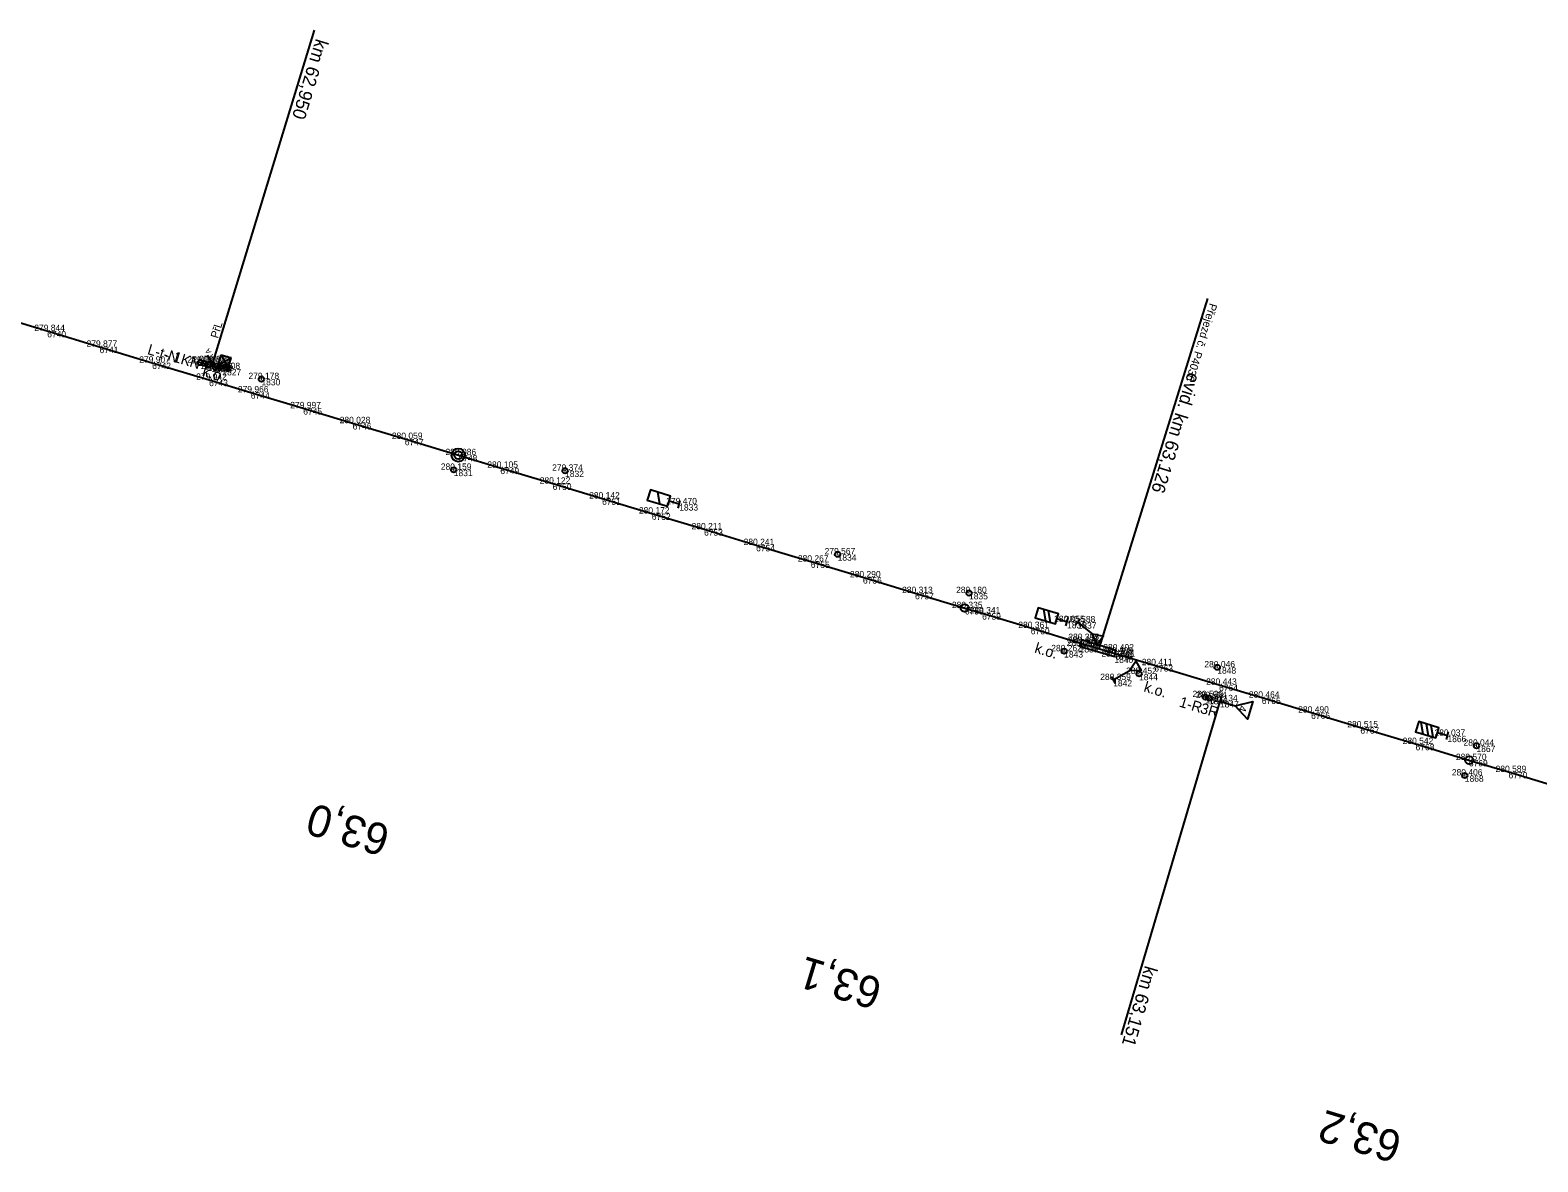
# Model space of a CAD drawing. Extents: x -613968 to -612840, y -1056667 to -1056202.
# Drawn here: x -613407.7 to -613122.4, y -1056605.8 to -1056391.6 of the extents above; entities that cross this region are included whole.
import ezdxf

# ---------------------------------------------------------------- set-up
doc = ezdxf.new("R2010")
doc.units = 0
for name, color, linetype in [('Deska žb', 7, 'Continuous'), ('Rozpiska_pole_2', 7, 'Continuous'), ('Rozpiska_pole_5', 7, 'Continuous'), ('Rozpiska_pole_7', 7, 'Continuous'), ('Vrstva 1', 7, 'Continuous'), ('Vrstva 27', 7, 'Continuous'), ('Vrstva 49', 7, 'Continuous'), ('Vrstva 50', 7, 'Continuous'), ('Vrstva 60', 7, 'Continuous'), ('Vrstva 61', 7, 'Continuous')]:
    doc.layers.add(name, color=color, linetype=linetype)

msp = doc.modelspace()

# ---------------------------------------------------------------- linework, layer by layer
for p, q in [((-613205.42, -1056508.66), (-613184.86, -1056442.36)), ((-613208.99, -1056503.07), (-613209.96, -1056504.28)), ((-613203.12, -1056513.92), (-613202.36, -1056515.28))]:
    msp.add_line(p, q)
for points in [[(-613209.47, -1056503.68), (-613206.75, -1056505.84), (-613204.56, -1056506.31), (-613205.8, -1056507.88), (-613206.75, -1056505.84)], [(-613202.74, -1056514.6), (-613199.72, -1056512.89), (-613198.45, -1056511.05), (-613197.47, -1056512.78), (-613199.72, -1056512.89)]]:
    msp.add_lwpolyline(points)
msp.add_lwpolyline([(-613208.77, -1056507.03), (-613209.1, -1056508.19), (-613202.51, -1056510.17), (-613202.17, -1056509.01)], close=True)
at = {"layer": 'Deska žb'}
for p, q in [((-613182.54, -1056518.62), (-613201.21, -1056581.77)), ((-613182.33, -1056517.9), (-613182.76, -1056519.33))]:
    msp.add_line(p, q, dxfattribs=at)
msp.add_lwpolyline([(-613182.54, -1056518.62), (-613179.67, -1056519.48), (-613176.29, -1056518.67), (-613177.31, -1056522.02), (-613179.67, -1056519.48)], dxfattribs=at)
at = {"layer": 'Rozpiska_pole_2'}
msp.add_lwpolyline([(-613373.29, -1056454.43), (-613373.43, -1056455.09), (-613373.04, -1056455.18), (-613372.84, -1056454.6)], close=True, dxfattribs=at)
at = {"layer": 'Rozpiska_pole_5'}
for p, q in [((-613373.19, -1056454.81), (-613353.93, -1056391.59)), ((-613374.19, -1056453.11), (-613373.19, -1056454.81)), ((-613373.62, -1056455.07), (-613372.76, -1056454.56))]:
    msp.add_line(p, q, dxfattribs=at)
at = {"layer": 'Rozpiska_pole_7'}
for p, q in [((-613372.15, -1056454.97), (-613371.57, -1056453.05)), ((-613372.15, -1056454.97), (-613369.66, -1056453.63)), ((-613371.57, -1056453.05), (-613369.66, -1056453.63)), ((-613371.57, -1056453.05), (-613370.24, -1056455.55)), ((-613370.24, -1056455.55), (-613369.66, -1056453.63)), ((-613372.06, -1056455.52), (-613372.53, -1056455.38)), ((-613372.15, -1056454.97), (-613372.3, -1056455.45)), ((-613372.15, -1056454.97), (-613370.24, -1056455.55)), ((-613370.14, -1056456.1), (-613370.62, -1056455.95)), ((-613370.24, -1056455.55), (-613370.38, -1056456.03)), ((-613327.6, -1056474.81), (-613327.5, -1056474.83)), ((-613288.52, -1056481.28), (-613288.9, -1056479.07)), ((-613285.1, -1056482.05), (-613284.67, -1056480.61)), ((-613230.07, -1056498.14), (-613229.98, -1056498.17)), ((-613215.96, -1056501.22), (-613215.58, -1056503.43)), ((-613214.62, -1056503.72), (-613215, -1056501.51)), ((-613211.68, -1056504.34), (-613211.25, -1056502.91)), ((-613144.07, -1056524.83), (-613144.46, -1056522.63)), ((-613143.5, -1056522.92), (-613143.12, -1056525.12)), ((-613142.16, -1056525.41), (-613142.54, -1056523.2)), ((-613139.69, -1056525.89), (-613139.26, -1056524.45)), ((-613136.25, -1056532.67), (-613136.16, -1056532.69))]:
    msp.add_line(p, q, dxfattribs=at)
for points in [[(-613284.88, -1056481.33), (-613286.8, -1056480.75), (-613286.51, -1056479.8), (-613290.34, -1056478.64), (-613290.92, -1056480.55), (-613287.09, -1056481.71), (-613286.8, -1056480.75)], [(-613211.46, -1056503.63), (-613213.38, -1056503.05), (-613213.09, -1056502.09), (-613216.92, -1056500.93), (-613217.5, -1056502.85), (-613213.67, -1056504), (-613213.38, -1056503.05)], [(-613139.48, -1056525.17), (-613141.39, -1056524.59), (-613141.1, -1056523.64), (-613144.93, -1056522.48), (-613145.51, -1056524.4), (-613141.68, -1056525.55), (-613141.39, -1056524.59)]]:
    msp.add_lwpolyline(points, dxfattribs=at)
for centre, radius in [((-613326.7, -1056472.03), 1.25), ((-613326.7, -1056472.03), 0.752), ((-613327.55, -1056474.82), 0.5), ((-613230.03, -1056498.15), 0.5), ((-613230.86, -1056500.98), 0.75), ((-613135.36, -1056529.78), 0.75), ((-613136.2, -1056532.68), 0.5)]:
    msp.add_circle(centre, radius, dxfattribs=at)
at = {"layer": 'Vrstva 1'}
msp.add_lwpolyline([(-613412.28, -1056446.19), (-613404.49, -1056448.54), (-613394.59, -1056451.53), (-613384.63, -1056454.54), (-613373.86, -1056457.78), (-613365.96, -1056460.17), (-613356.04, -1056463.16), (-613346.69, -1056465.99), (-613336.81, -1056468.97), (-613326.66, -1056472.04), (-613318.74, -1056474.43), (-613308.83, -1056477.43), (-613299.48, -1056480.25), (-613290.06, -1056483.09), (-613280.18, -1056486.08), (-613270.33, -1056489.06), (-613259.97, -1056492.18), (-613250.11, -1056495.17), (-613240.25, -1056498.15), (-613230.81, -1056501), (-613227.56, -1056501.98), (-613218.35, -1056504.76), (-613208.92, -1056507.61), (-613202.34, -1056509.59), (-613194.98, -1056511.8), (-613182.71, -1056515.51), (-613174.62, -1056517.95), (-613165.28, -1056520.77), (-613155.97, -1056523.57), (-613145.52, -1056526.72), (-613135.43, -1056529.76), (-613127.92, -1056532.02), (-613117.96, -1056535.02)], dxfattribs=at)
at = {"layer": 'Vrstva 27'}
for p, q in [((-613375.54, -1056454.57), (-613375.52, -1056454.47)), ((-613374.84, -1056454.69), (-613374.77, -1056454.62)), ((-613374.15, -1056454.9), (-613374.05, -1056454.93)), ((-613212.07, -1056509.14), (-613211.97, -1056509.17)), ((-613197.9, -1056513.43), (-613197.8, -1056513.46)), ((-613185.34, -1056517.83), (-613185.24, -1056517.86)), ((-613184.67, -1056518.01), (-613184.57, -1056518.04))]:
    msp.add_line(p, q, dxfattribs=at)
for centre in [(-613375.53, -1056454.52), (-613374.81, -1056454.66), (-613374.1, -1056454.91), (-613212.02, -1056509.16), (-613197.85, -1056513.45), (-613185.29, -1056517.85), (-613184.62, -1056518.02)]:
    msp.add_circle(centre, 0.5, dxfattribs=at)
at = {"layer": 'Vrstva 49'}
for p, q in [((-613373.42, -1056454.98), (-613372.98, -1056454.75)), ((-613373.32, -1056454.65), (-613373.08, -1056455.09))]:
    msp.add_line(p, q, dxfattribs=at)
at = {"layer": 'Vrstva 50'}
for p, q in [((-613363.99, -1056457.62), (-613363.9, -1056457.65)), ((-613306.53, -1056474.97), (-613306.43, -1056475)), ((-613254.95, -1056490.81), (-613254.86, -1056490.84)), ((-613183.08, -1056512.2), (-613182.99, -1056512.23)), ((-613134.04, -1056527.04), (-613133.95, -1056527.07))]:
    msp.add_line(p, q, dxfattribs=at)
for centre in [(-613363.95, -1056457.64), (-613306.48, -1056474.99), (-613254.9, -1056490.82), (-613183.04, -1056512.21), (-613133.99, -1056527.05)]:
    msp.add_circle(centre, 0.5, dxfattribs=at)
at = {"layer": 'Vrstva 60'}
for p, q in [((-613404.49, -1056448.54), (-613404.49, -1056448.54)), ((-613394.59, -1056451.53), (-613394.59, -1056451.53)), ((-613384.63, -1056454.54), (-613384.63, -1056454.54)), ((-613375.53, -1056454.52), (-613375.53, -1056454.52)), ((-613374.81, -1056454.66), (-613374.81, -1056454.66)), ((-613374.1, -1056454.91), (-613374.1, -1056454.91)), ((-613373.43, -1056455.09), (-613373.43, -1056455.09)), ((-613373.29, -1056454.43), (-613373.29, -1056454.43)), ((-613373.2, -1056454.87), (-613373.2, -1056454.87)), ((-613373.19, -1056454.81), (-613373.19, -1056454.81)), ((-613373.04, -1056455.18), (-613373.04, -1056455.18)), ((-613372.84, -1056454.6), (-613372.84, -1056454.6)), ((-613371.34, -1056455.74), (-613371.34, -1056455.74)), ((-613373.86, -1056457.78), (-613373.86, -1056457.78)), ((-613363.95, -1056457.64), (-613363.95, -1056457.64)), ((-613365.96, -1056460.17), (-613365.96, -1056460.17)), ((-613356.04, -1056463.16), (-613356.04, -1056463.16)), ((-613346.69, -1056465.99), (-613346.69, -1056465.99)), ((-613336.81, -1056468.97), (-613336.81, -1056468.97)), ((-613326.66, -1056472.04), (-613326.66, -1056472.04)), ((-613327.55, -1056474.82), (-613327.55, -1056474.82)), ((-613318.74, -1056474.43), (-613318.74, -1056474.43)), ((-613306.48, -1056474.99), (-613306.48, -1056474.99)), ((-613308.83, -1056477.43), (-613308.83, -1056477.43)), ((-613299.48, -1056480.25), (-613299.48, -1056480.25)), ((-613284.88, -1056481.33), (-613284.88, -1056481.33)), ((-613290.06, -1056483.09), (-613290.06, -1056483.09)), ((-613280.18, -1056486.08), (-613280.18, -1056486.08)), ((-613270.33, -1056489.06), (-613270.33, -1056489.06)), ((-613254.9, -1056490.82), (-613254.9, -1056490.82)), ((-613259.97, -1056492.18), (-613259.97, -1056492.18)), ((-613250.11, -1056495.17), (-613250.11, -1056495.17)), ((-613240.25, -1056498.15), (-613240.25, -1056498.15)), ((-613230.03, -1056498.15), (-613230.03, -1056498.15)), ((-613230.81, -1056501), (-613230.81, -1056501)), ((-613227.56, -1056501.98), (-613227.56, -1056501.98)), ((-613218.35, -1056504.76), (-613218.35, -1056504.76)), ((-613211.46, -1056503.63), (-613211.46, -1056503.63)), ((-613209.47, -1056503.68), (-613209.47, -1056503.68)), ((-613209.1, -1056508.19), (-613209.1, -1056508.19)), ((-613208.92, -1056507.61), (-613208.92, -1056507.61)), ((-613208.77, -1056507.03), (-613208.77, -1056507.03)), ((-613212.02, -1056509.16), (-613212.02, -1056509.16)), ((-613202.51, -1056510.17), (-613202.51, -1056510.17)), ((-613202.34, -1056509.59), (-613202.34, -1056509.59)), ((-613202.17, -1056509.01), (-613202.17, -1056509.01)), ((-613197.85, -1056513.45), (-613197.85, -1056513.45)), ((-613194.98, -1056511.8), (-613194.98, -1056511.8)), ((-613183.04, -1056512.21), (-613183.04, -1056512.21)), ((-613202.74, -1056514.6), (-613202.74, -1056514.6)), ((-613182.71, -1056515.51), (-613182.71, -1056515.51)), ((-613185.29, -1056517.85), (-613185.29, -1056517.85)), ((-613184.62, -1056518.02), (-613184.62, -1056518.02)), ((-613182.54, -1056518.62), (-613182.54, -1056518.62)), ((-613174.62, -1056517.95), (-613174.62, -1056517.95)), ((-613165.28, -1056520.77), (-613165.28, -1056520.77)), ((-613155.97, -1056523.57), (-613155.97, -1056523.57)), ((-613139.48, -1056525.17), (-613139.48, -1056525.17)), ((-613145.52, -1056526.72), (-613145.52, -1056526.72)), ((-613133.99, -1056527.05), (-613133.99, -1056527.05)), ((-613135.43, -1056529.76), (-613135.43, -1056529.76)), ((-613136.2, -1056532.68), (-613136.2, -1056532.68)), ((-613127.92, -1056532.02), (-613127.92, -1056532.02))]:
    msp.add_line(p, q, dxfattribs=at)

# ---------------------------------------------------------------- texts
for s, height, p in [('Přejezd č. P4036', 1.5, (-613184.46, -1056443.18)), ('evid. km 63,126', 2.5, (-613188.58, -1056456.23))]:
    msp.add_text(s, height=height, rotation=252.7728).set_placement(p)
at = {"layer": 'Deska žb'}
for s, height, rotation, p in [('4', 1.5, 253.2104, (-613178.83, -1056519.28)), ('km 63,151', 2.5, 253.5345, (-613196.71, -1056568.55))]:
    msp.add_text(s, height=height, rotation=rotation, dxfattribs=at).set_placement(p)
at = {"layer": 'Rozpiska_pole_5'}
for s, height, rotation, p in [('km 62,950', 2.5, 253.059, (-613353.63, -1056393.08)), ('PřL', 1.5, 73.059, (-613372.19, -1056450.03)), ('  A A ', 1, 120.5059, (-613372.33, -1056454.31))]:
    msp.add_text(s, height=height, rotation=rotation, dxfattribs=at).set_placement(p)
at = {"layer": 'Rozpiska_pole_7'}
for s, rotation, p in [('63,0', 163.1761, (-613339.25, -1056542.36)), ('63,1', 163.1878, (-613246.12, -1056571.37)), ('63,2', 163.2403, (-613147.73, -1056600.41))]:
    msp.add_text(s, height=6, rotation=rotation, dxfattribs=at).set_placement(p)
at = {"layer": 'Vrstva 27'}
for s, rotation, p in [('L-t-N', 343.2314, (-613385.67, -1056452.88)), ('1KN', 343.2044, (-613380.81, -1056454.29)), ('k.o.', 343.2314, (-613375.29, -1056456.99)), ('k.o.', 343.1899, (-613217.76, -1056509.38)), ('k.o.', 343.2294, (-613197.09, -1056516.74)), ('1-R', 343.1971, (-613190.39, -1056519.61)), ('3R', 343.2104, (-613186.41, -1056520.8))]:
    msp.add_text(s, height=2, rotation=rotation, dxfattribs=at).set_placement(p)
at = {"layer": 'Vrstva 60'}
for s, p in [('6740', (-613404.49, -1056449.74)), ('6741', (-613394.59, -1056452.73)), ('1826', (-613373.29, -1056455.63)), ('6742', (-613384.63, -1056455.74)), ('1818', (-613375.53, -1056455.72)), ('1819', (-613374.81, -1056455.86)), ('1820', (-613374.1, -1056456.11)), ('1823', (-613373.43, -1056456.29)), ('1822', (-613373.2, -1056456.07)), ('1821', (-613373.19, -1056456.01)), ('1824', (-613373.04, -1056456.38)), ('1825', (-613372.84, -1056455.8)), ('1827', (-613371.34, -1056456.94)), ('6743', (-613373.86, -1056458.98)), ('1830', (-613363.95, -1056458.83)), ('6744', (-613365.96, -1056461.37)), ('6745', (-613356.04, -1056464.36)), ('6746', (-613346.69, -1056467.19)), ('6747', (-613336.81, -1056470.17)), ('6748', (-613326.66, -1056473.24)), ('1831', (-613327.55, -1056476.02)), ('6749', (-613318.74, -1056475.63)), ('1832', (-613306.48, -1056476.19)), ('6750', (-613308.83, -1056478.63)), ('6751', (-613299.48, -1056481.45)), ('1833', (-613284.88, -1056482.53)), ('6752', (-613290.06, -1056484.29)), ('6753', (-613280.18, -1056487.28)), ('6754', (-613270.33, -1056490.26)), ('1834', (-613254.9, -1056492.02)), ('6755', (-613259.97, -1056493.38)), ('6756', (-613250.11, -1056496.36)), ('6757', (-613240.25, -1056499.34)), ('1835', (-613230.03, -1056499.35)), ('6758', (-613230.81, -1056502.2)), ('6759', (-613227.56, -1056503.18)), ('6760', (-613218.35, -1056505.96)), ('1836', (-613211.46, -1056504.83)), ('1837', (-613209.47, -1056504.88)), ('1839', (-613209.1, -1056509.39)), ('6761', (-613208.92, -1056508.81)), ('1838', (-613208.77, -1056508.23)), ('1843', (-613212.02, -1056510.35)), ('1840', (-613202.51, -1056511.37)), ('6762', (-613202.34, -1056510.79)), ('1841', (-613202.17, -1056510.21)), ('1844', (-613197.85, -1056514.65)), ('6763', (-613194.98, -1056513)), ('1848', (-613183.04, -1056513.41)), ('1842', (-613202.74, -1056515.8)), ('6764', (-613182.71, -1056516.71)), ('1845', (-613185.29, -1056519.05)), ('1846', (-613184.62, -1056519.22)), ('1847', (-613182.54, -1056519.81)), ('6765', (-613174.62, -1056519.15)), ('6766', (-613165.28, -1056521.97)), ('6767', (-613155.97, -1056524.77)), ('1866', (-613139.48, -1056526.37)), ('6768', (-613145.52, -1056527.92)), ('1867', (-613133.99, -1056528.25)), ('6769', (-613135.43, -1056530.96)), ('1868', (-613136.2, -1056533.88)), ('6770', (-613127.92, -1056533.22))]:
    msp.add_text(s, height=1.2, dxfattribs=at).set_placement(p)
at = {"layer": 'Vrstva 61'}
for s, p in [('279.844', (-613406.94, -1056448.54)), ('279.877', (-613397.05, -1056451.53)), ('279.907', (-613387.08, -1056454.54)), ('279.733', (-613377.98, -1056454.52)), ('279.687', (-613377.26, -1056454.66)), ('279.686', (-613376.55, -1056454.91)), ('279.191', (-613375.78, -1056455.09)), ('279.140', (-613375.74, -1056454.43)), ('279.206', (-613375.65, -1056454.87)), ('279.206', (-613375.64, -1056454.81)), ('279.191', (-613375.4, -1056455.18)), ('279.157', (-613375.29, -1056454.6)), ('279.942', (-613376.31, -1056457.78)), ('279.308', (-613373.79, -1056455.74)), ('279.178', (-613366.4, -1056457.64)), ('279.966', (-613368.41, -1056460.17)), ('279.997', (-613358.49, -1056463.16)), ('280.028', (-613349.14, -1056465.99)), ('280.059', (-613339.26, -1056468.97)), ('280.086', (-613329.11, -1056472.04)), ('280.159', (-613330, -1056474.82)), ('280.105', (-613321.2, -1056474.43)), ('279.374', (-613308.93, -1056474.99)), ('280.122', (-613311.28, -1056477.43)), ('280.142', (-613301.93, -1056480.25)), ('280.172', (-613292.51, -1056483.09)), ('279.470', (-613287.33, -1056481.33)), ('280.211', (-613282.54, -1056486.08)), ('280.241', (-613272.69, -1056489.06)), ('280.267', (-613262.42, -1056492.18)), ('279.567', (-613257.36, -1056490.82)), ('280.290', (-613252.56, -1056495.17)), ('280.313', (-613242.7, -1056498.15)), ('280.180', (-613232.48, -1056498.15)), ('280.335', (-613233.27, -1056501)), ('280.341', (-613229.91, -1056501.98)), ('280.055', (-613213.92, -1056503.63)), ('280.588', (-613211.93, -1056503.68)), ('280.361', (-613220.7, -1056504.76)), ('280.262', (-613214.47, -1056509.16)), ('280.393', (-613211.55, -1056508.19)), ('280.404', (-613211.37, -1056507.61)), ('280.395', (-613211.23, -1056507.03)), ('280.409', (-613204.79, -1056509.59)), ('280.402', (-613204.62, -1056509.01)), ('280.398', (-613204.97, -1056510.17)), ('280.411', (-613197.33, -1056511.8)), ('280.046', (-613185.49, -1056512.21)), ('280.359', (-613205.2, -1056514.6)), ('280.452', (-613200.3, -1056513.45)), ('280.443', (-613185.16, -1056515.51)), ('280.539', (-613187.74, -1056517.85)), ('280.504', (-613187.07, -1056518.02)), ('280.464', (-613177.07, -1056517.95)), ('280.134', (-613184.99, -1056518.62)), ('280.490', (-613167.73, -1056520.77)), ('280.515', (-613158.43, -1056523.57)), ('280.542', (-613147.96, -1056526.72)), ('280.037', (-613141.93, -1056525.17)), ('280.570', (-613137.88, -1056529.76)), ('280.044', (-613136.44, -1056527.05)), ('280.589', (-613130.37, -1056532.02)), ('280.406', (-613138.65, -1056532.68))]:
    msp.add_text(s, height=1.2, dxfattribs=at).set_placement(p)

doc.saveas('drawing.dxf')
